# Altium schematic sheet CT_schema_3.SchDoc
size 334 x 183 mm
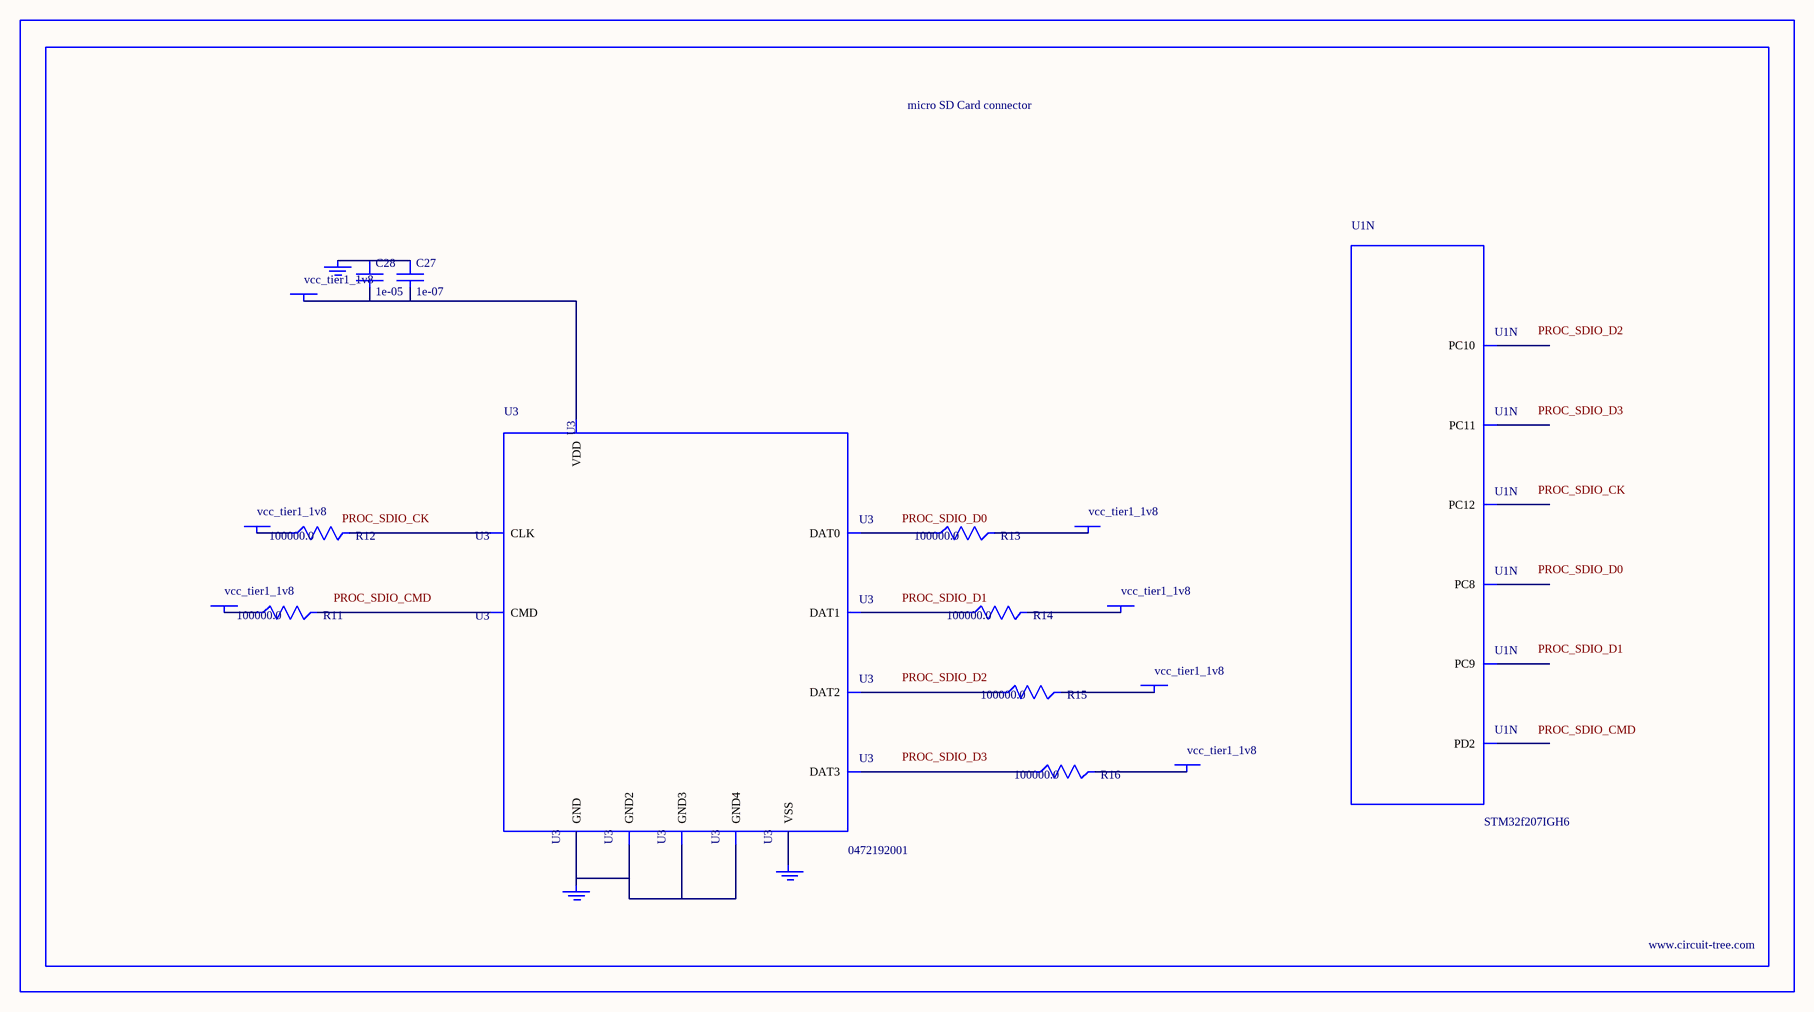
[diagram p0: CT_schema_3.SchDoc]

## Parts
BORDER2  (no value)
C27  1e-07  [C0402]
C28  1e-05  [C0805]
GND_INSTANCE_2_0  (no value)
GND_INSTANCE_2_1  (no value)
GND_INSTANCE_2_2  (no value)
POWER_INSTANCE_2_0  vcc_tier1_1v8
POWER_INSTANCE_2_1  vcc_tier1_1v8
POWER_INSTANCE_2_2  vcc_tier1_1v8
POWER_INSTANCE_2_3  vcc_tier1_1v8
POWER_INSTANCE_2_4  vcc_tier1_1v8
POWER_INSTANCE_2_5  vcc_tier1_1v8
POWER_INSTANCE_2_6  vcc_tier1_1v8
R11  100000.0  [R0603]
R12  100000.0  [R0603]
R13  100000.0  [R0603]
R14  100000.0  [R0603]
R15  100000.0  [R0603]
R16  100000.0  [R0603]
U1  STM32f207IGH6  [UFBGA176_25]  (part N of 16)
U3  0472192001  [MOLEX_47219-2001]

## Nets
NetC27_1: C27.1 C28.1 GND_INSTANCE_2_0.0(GND)
NetC27_2: C27.2 C28.2 POWER_INSTANCE_2_3.0(PWR) U3.4(VDD)
NetGND_INSTANCE_2_1_0: GND_INSTANCE_2_1.0(GND) U3.6(VSS)
NetGND_INSTANCE_2_2_0: GND_INSTANCE_2_2.0(GND) U3.G1(GND) U3.G2(GND2) U3.G3(GND3) U3.G4(GND4)
NetPOWER_INSTANCE_2_0_0: POWER_INSTANCE_2_0.0(PWR) R15.2
NetPOWER_INSTANCE_2_1_0: POWER_INSTANCE_2_1.0(PWR) R16.2
NetPOWER_INSTANCE_2_2_0: POWER_INSTANCE_2_2.0(PWR) R11.1
NetPOWER_INSTANCE_2_4_0: POWER_INSTANCE_2_4.0(PWR) R12.1
NetPOWER_INSTANCE_2_5_0: POWER_INSTANCE_2_5.0(PWR) R13.2
NetPOWER_INSTANCE_2_6_0: POWER_INSTANCE_2_6.0(PWR) R14.2
NetR11_2: R11.2 U3.3(CMD)
NetR12_2: R12.2 U3.5(CLK)
NetR13_1: R13.1 U3.7(DAT0)
NetR14_1: R14.1 U3.8(DAT1)
NetR15_1: R15.1 U3.1(DAT2)
NetR16_1: R16.1 U3.2(DAT3)

Not connected (* = marked no-connect by the designer): U1 A12(PC12) B13(PC11) B14(PC10) D12(PD2) F14(PC9) G14(PC8)

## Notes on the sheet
- Labels drawn without touching a wire or pin: PROC_SDIO_CK, PROC_SDIO_CMD, PROC_SDIO_D0, PROC_SDIO_D1, PROC_SDIO_D2, PROC_SDIO_D3

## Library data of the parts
BORDER2 = BORDER_PAGE2
C27 = C0402C104K3RACTU
C28 = C0805C106K8RACTU
GND_INSTANCE_2_0-GND_INSTANCE_2_2 = GND
POWER_INSTANCE_2_0-POWER_INSTANCE_2_6 = PWR
R11-R16 = RC0603JR-07100KL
